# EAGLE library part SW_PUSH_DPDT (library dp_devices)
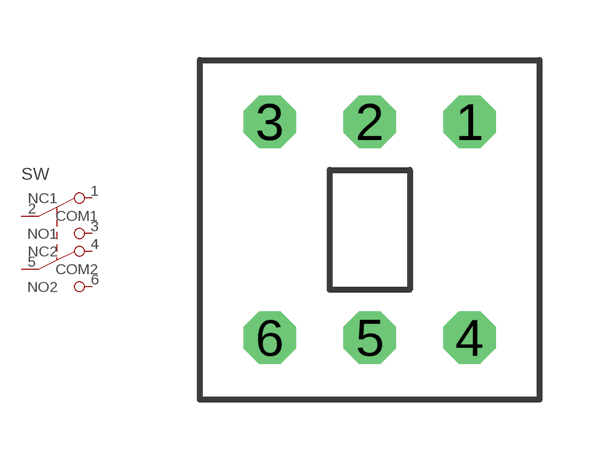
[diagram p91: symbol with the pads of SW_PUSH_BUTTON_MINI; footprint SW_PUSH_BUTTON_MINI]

Designator prefix SW

## SW_PUSH_DPDT  [SW_PUSH_BUTTON_MINI]
1  NC1  pas
2  COM1  pas
3  NO1  pas
4  NC2  pas
5  COM2  pas
6  NO2  pas

## Footprint SW_PUSH_BUTTON_MINI (pad centres in mm)
drill 0.8 octagon: 1 2.5,2.7; 2 0,2.7; 3 -2.5,2.7; 4 2.5,-2.7; 5 0,-2.7; 6 -2.5,-2.7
